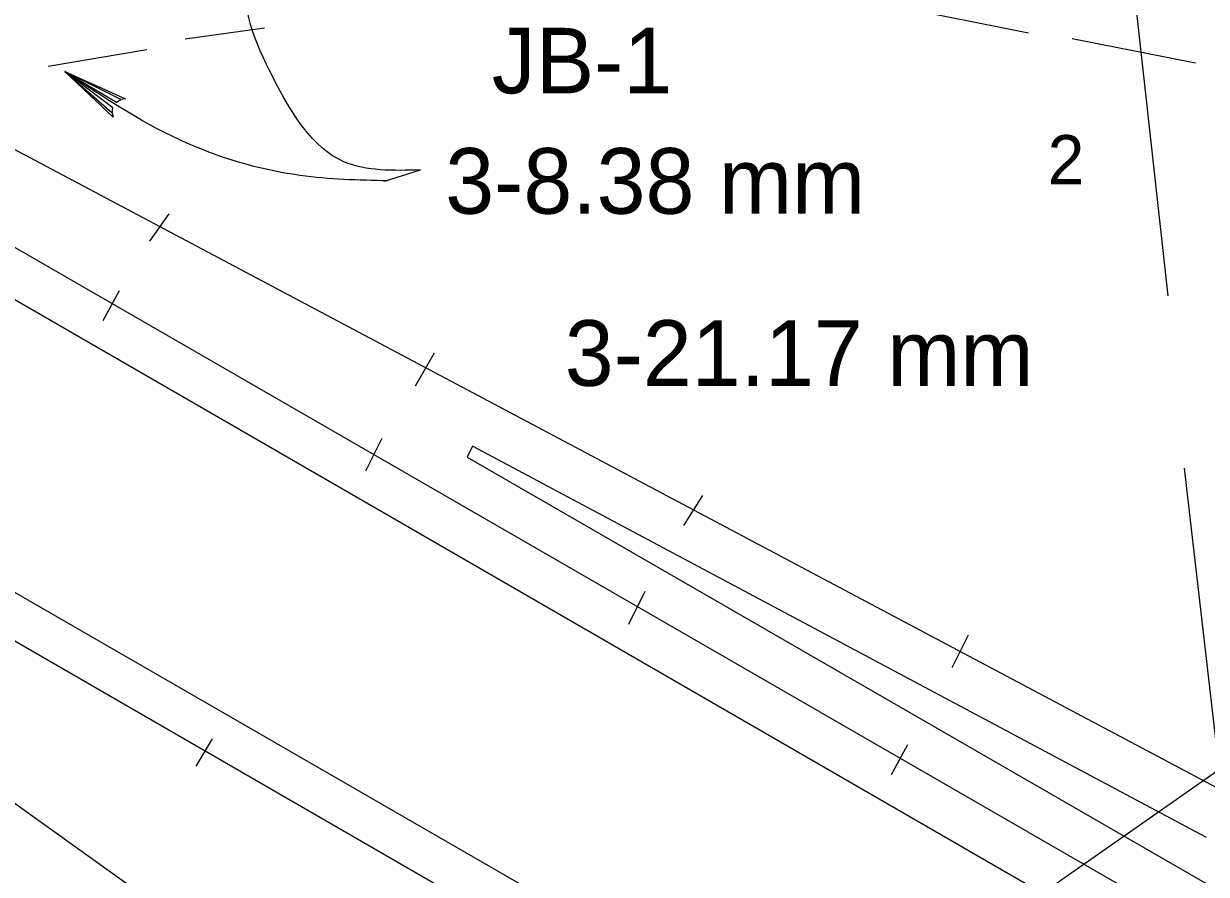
# Model space of a CAD drawing. Extents: x 36 to 2622, y -5330 to 219.
# Drawn here: x 2121.5 to 2175.5, y -4415.8 to -4376.9 of the extents above; entities that cross this region are included whole.
import ezdxf

# ---------------------------------------------------------------- set-up
doc = ezdxf.new("R2010")
doc.units = 0
doc.layers.add('2', color=7, linetype='Continuous')
doc.layers.add('3', color=7, linetype='Continuous')

# ---------------------------------------------------------------- blocks, each defined once
blk = doc.blocks.new('RARROW')
at = {"layer": '3'}
blk.add_lwpolyline([(-2.2695, 0.285), (-2.184875, 0.12075), (0, 0), (-2.2695, 0.285), (-2.38575, 0.384625), (0, 0), (-2.183125, -0.108), (-2.262875, -0.2705), (0, 0), (-2.38575, -0.379125), (-2.262875, -0.2705)], dxfattribs=at)

msp = doc.modelspace()

# ---------------------------------------------------------------- linework, layer by layer
at = {"layer": '2'}
for p, q in [((2538.009, -4157.413), (1748.46, -4710.544)), ((2173.731, -4389.33), (2171.481, -4368.83)), ((2167.356, -4377.33), (2161.106, -4376.08)), ((2128.856, -4377.58), (2132.481, -4377.08)), ((2174.981, -4378.705), (2169.356, -4377.58)), ((2122.606, -4378.83), (2127.106, -4378.08)), ((2176.481, -4412.08), (2115.981, -4379.955)), ((2381.856, -4540.205), (2110.356, -4383.33)), ((2137.95, -4384.097), (2139.606, -4383.58)), ((2382.981, -4538.33), (2117.106, -4384.83)), ((2128.106, -4385.58), (2127.231, -4386.83)), ((2125.106, -4390.455), (2125.856, -4389.08)), ((2376.106, -4550.08), (2099.106, -4390.205)), ((2375.106, -4551.83), (2096.981, -4391.205)), ((2140.231, -4391.955), (2139.356, -4393.455)), ((2131.981, -4420.33), (2093.481, -4392.83)), ((2137.106, -4397.33), (2137.856, -4395.83)), ((2141.981, -4396.205), (2141.731, -4396.705)), ((2175.481, -4414.08), (2141.981, -4396.205)), ((2141.731, -4396.705), (2268.356, -4469.83)), ((2190.606, -4537.205), (2174.481, -4397.205)), ((2152.481, -4398.455), (2151.606, -4399.83)), ((2149.106, -4404.33), (2149.856, -4402.83)), ((2164.606, -4404.83), (2163.856, -4406.33)), ((2129.356, -4410.83), (2130.106, -4409.58)), ((2161.106, -4411.205), (2161.856, -4409.83))]:
    msp.add_line(p, q, dxfattribs=at)
for points in [[(2139.606, -4383.58), (2136.106, -4383.205), (2132.856, -4379.33), (2131.731, -4374.58), (2134.606, -4371.455), (2137.856, -4370.705), (2139.595, -4370.208)], [(2138.106, -4384.08), (2134.106, -4383.83), (2128.606, -4382.205), (2123.356, -4379.08)]]:
    msp.add_spline(points, degree=3, dxfattribs=at)

# ---------------------------------------------------------------- block references
at = {"layer": '2', "xscale": 1.2574347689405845, "yscale": 1.3092961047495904, "rotation": 146.24555304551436}
msp.add_blockref('RARROW', (2123.356, -4379.079), dxfattribs=at)

# ---------------------------------------------------------------- texts
at = {"layer": '2'}
msp.add_text('JB-1', height=2.9955, dxfattribs=at).set_placement((2142.856, -4380.079))
for s, height, rotation, p in [('2', 2.25, 0.0055, (2168.238, -4384.235)), ('3-8.38 mm', 3, 360, (2140.731, -4385.579)), ('3-21.17 mm', 3, 360, (2146.187, -4393.445))]:
    msp.add_text(s, height=height, rotation=rotation, dxfattribs=at).set_placement(p)

doc.saveas('drawing.dxf')
